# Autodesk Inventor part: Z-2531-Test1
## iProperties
Created: 2009-11
Part Number: Z-2531-Test1
Material: VA 1.4301 III c
Document SubType Name: Blech
Designer: Strathkötter
Density: 8.08 g/cm^3
Mass: 15387.5 g
Surface Area: 9685.6 cm^2
Volume: 1904.4 cm^3
Author: Strathkötter
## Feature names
1. Trennen1
2. Grobblech1
3. Grobblech2
4. Biegung1
5. Grobblech3
6. Biegung2
